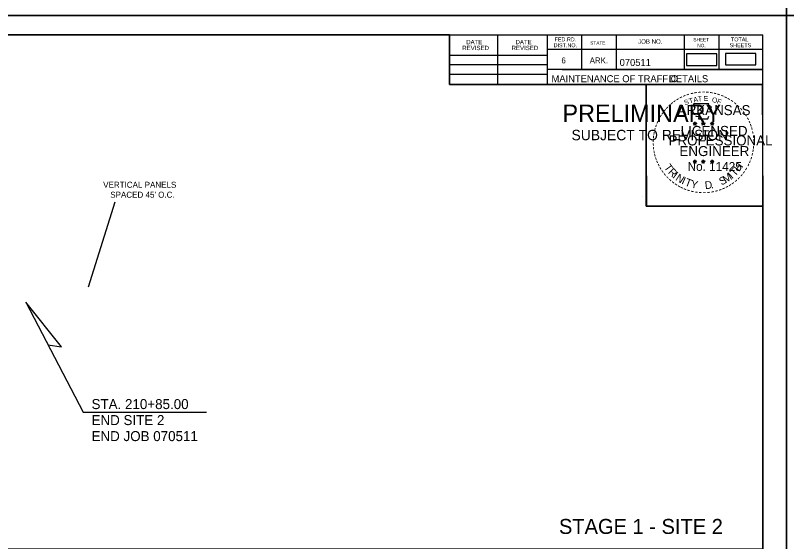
# Model space of a CAD drawing. Extents: x 1398460 to 1408037, y 380768 to 383968.
# Drawn here: x 1401561 to 1402332, y 381308 to 381834 of the extents above; entities that cross this region are included whole.
import ezdxf

# ---------------------------------------------------------------- set-up
doc = ezdxf.new("R2010")
doc.units = 0
for name, color, linetype in [('Default', 7, 'Continuous'), ('MOT STAGE ALL', 7, 'Continuous'), ('R_Border', 7, 'Continuous'), ('R_Border PE', 7, 'Continuous'), ('R_Border Prem', 7, 'Continuous'), ('R_Dimension', 7, 'Continuous'), ('R_MOT', 7, 'Continuous'), ('R_No Plot', 7, 'Continuous')]:
    doc.layers.add(name, color=color, linetype=linetype)

msp = doc.modelspace()

# ---------------------------------------------------------------- linework, layer by layer
at = {"layer": 'Default'}
for p, q in [((1401571.6, 381547.85), (1401628.93, 381437.94)), ((1401628.93, 381437.94), (1401752.42, 381437.94))]:
    msp.add_line(p, q, dxfattribs=at)
msp.add_lwpolyline([(1401593.87, 381505.15), (1401607.48, 381503.17), (1401571.6, 381547.85)], dxfattribs=at)
at = {"layer": 'R_Border'}
for p, q in [((1400727.57, 381814.73), (1402308.47, 381814.73)), ((1401995.27, 381765.33), (1401995.27, 381814.73)), ((1402043.67, 381765.33), (1402043.67, 381814.73)), ((1402092.97, 381814.73), (1402092.97, 381765.33)), ((1402127.17, 381814.73), (1402127.17, 381780.03)), ((1402161.87, 381814.73), (1402161.87, 381780.03)), ((1402229.77, 381814.73), (1402229.77, 381780.03)), ((1402264.47, 381814.73), (1402264.47, 381780.03)), ((1402308.47, 380787.43), (1402308.47, 381814.73)), ((1402308.47, 381800.03), (1402092.97, 381800.03)), ((1402308.47, 381800.13), (1402308.47, 381800.13)), ((1401995.27, 381794.63), (1402092.97, 381794.63)), ((1401995.27, 381785.33), (1402092.97, 381785.33)), ((1401995.27, 381775.63), (1402092.97, 381775.63)), ((1402308.47, 381780.03), (1402092.97, 381780.03)), ((1402107.77, 381780.03), (1402308.47, 381780.03)), ((1402308.47, 381765.33), (1401995.27, 381765.33))]:
    msp.add_line(p, q, dxfattribs=at)
at = {"layer": 'R_Border PE'}
for p, q in [((1402238.89, 381726.61), (1402240.64, 381726.05)), ((1402238.89, 381726.61), (1402240.16, 381726.38)), ((1402238.89, 381726.61), (1402240.08, 381726)), ((1402239.56, 381724.57), (1402240.64, 381726.05)), ((1402239.56, 381724.57), (1402240.19, 381725.79)), ((1402239.56, 381724.57), (1402240.63, 381725.65)), ((1402240.64, 381727.88), (1402240.43, 381726.62)), ((1402241.7, 381724.57), (1402240.63, 381725.64)), ((1402240.64, 381726.05), (1402240.64, 381727.88)), ((1402240.64, 381727.88), (1402240.88, 381726.63)), ((1402242.37, 381726.61), (1402240.64, 381726.05)), ((1402241.7, 381724.57), (1402240.64, 381726.05)), ((1402242.37, 381726.61), (1402240.94, 381726.36)), ((1402241.7, 381724.57), (1402241.02, 381726.02)), ((1402242.37, 381726.61), (1402241.35, 381726.1)), ((1402247.24, 381726.61), (1402248.99, 381726.05)), ((1402247.24, 381726.61), (1402248.51, 381726.38)), ((1402247.24, 381726.61), (1402248.43, 381726)), ((1402247.91, 381724.57), (1402248.99, 381726.05)), ((1402247.91, 381724.57), (1402248.54, 381725.79)), ((1402247.91, 381724.57), (1402248.98, 381725.65)), ((1402248.99, 381727.88), (1402248.78, 381726.62)), ((1402250.05, 381724.57), (1402248.98, 381725.64)), ((1402248.99, 381726.05), (1402248.99, 381727.88)), ((1402248.99, 381727.88), (1402249.23, 381726.63)), ((1402250.72, 381726.61), (1402248.99, 381726.05)), ((1402250.05, 381724.57), (1402248.99, 381726.05)), ((1402250.72, 381726.61), (1402249.29, 381726.36)), ((1402250.05, 381724.57), (1402249.37, 381726.02)), ((1402250.72, 381726.61), (1402249.7, 381726.1)), ((1402256.06, 381726.55), (1402257.81, 381725.99)), ((1402256.06, 381726.55), (1402257.33, 381726.32)), ((1402256.06, 381726.55), (1402257.25, 381725.94)), ((1402256.73, 381724.51), (1402257.81, 381725.99)), ((1402256.73, 381724.51), (1402257.36, 381725.73)), ((1402256.73, 381724.51), (1402257.8, 381725.59)), ((1402257.81, 381727.82), (1402257.6, 381726.56)), ((1402258.87, 381724.51), (1402257.8, 381725.58)), ((1402257.81, 381725.99), (1402257.81, 381727.82)), ((1402257.81, 381727.82), (1402258.05, 381726.57)), ((1402259.54, 381726.55), (1402257.81, 381725.99)), ((1402258.87, 381724.51), (1402257.81, 381725.99)), ((1402259.54, 381726.55), (1402258.11, 381726.3)), ((1402258.87, 381724.51), (1402258.19, 381725.96)), ((1402259.54, 381726.55), (1402258.52, 381726.04)), ((1402238.87, 381688.74), (1402240.62, 381688.19)), ((1402238.87, 381688.74), (1402240.14, 381688.52)), ((1402238.87, 381688.74), (1402240.06, 381688.13)), ((1402239.54, 381686.7), (1402240.62, 381688.19)), ((1402239.54, 381686.7), (1402240.17, 381687.92)), ((1402239.54, 381686.7), (1402240.61, 381687.79)), ((1402240.62, 381690.01), (1402240.41, 381688.75)), ((1402241.68, 381686.7), (1402240.61, 381687.77)), ((1402240.62, 381688.19), (1402240.62, 381690.01)), ((1402240.62, 381690.01), (1402240.86, 381688.76)), ((1402242.35, 381688.74), (1402240.62, 381688.19)), ((1402241.68, 381686.7), (1402240.62, 381688.19)), ((1402242.35, 381688.74), (1402240.92, 381688.5)), ((1402241.68, 381686.7), (1402241, 381688.16)), ((1402242.35, 381688.74), (1402241.33, 381688.23)), ((1402247.22, 381688.74), (1402248.96, 381688.19)), ((1402247.22, 381688.74), (1402248.48, 381688.52)), ((1402247.22, 381688.74), (1402248.4, 381688.13)), ((1402247.88, 381686.7), (1402248.96, 381688.19)), ((1402247.88, 381686.7), (1402248.51, 381687.92)), ((1402247.88, 381686.7), (1402248.95, 381687.79)), ((1402248.96, 381690.01), (1402248.76, 381688.75)), ((1402250.03, 381686.7), (1402248.95, 381687.77)), ((1402248.96, 381688.19), (1402248.96, 381690.01)), ((1402248.96, 381690.01), (1402249.21, 381688.76)), ((1402250.7, 381688.74), (1402248.96, 381688.19)), ((1402250.03, 381686.7), (1402248.96, 381688.19)), ((1402250.7, 381688.74), (1402249.27, 381688.5)), ((1402250.03, 381686.7), (1402249.34, 381688.16)), ((1402250.7, 381688.74), (1402249.68, 381688.23)), ((1402256.05, 381688.69), (1402257.8, 381688.14)), ((1402256.05, 381688.69), (1402257.32, 381688.47)), ((1402256.05, 381688.69), (1402257.24, 381688.08)), ((1402256.72, 381686.65), (1402257.8, 381688.14)), ((1402256.72, 381686.65), (1402257.35, 381687.87)), ((1402256.72, 381686.65), (1402257.79, 381687.74)), ((1402257.8, 381689.96), (1402257.59, 381688.7)), ((1402258.86, 381686.65), (1402257.79, 381687.72)), ((1402257.8, 381688.14), (1402257.8, 381689.96)), ((1402257.8, 381689.96), (1402258.04, 381688.71)), ((1402259.53, 381688.69), (1402257.8, 381688.14)), ((1402258.86, 381686.65), (1402257.8, 381688.14)), ((1402259.53, 381688.69), (1402258.1, 381688.45)), ((1402258.86, 381686.65), (1402258.18, 381688.11)), ((1402259.53, 381688.69), (1402258.51, 381688.18))]:
    msp.add_line(p, q, dxfattribs=at)
for points in [[(1402239.1, 381746), (1402240.44, 381741.86)], [(1402256.65, 381741.39), (1402257.36, 381742.81), (1402253.94, 381742.69), (1402254.68, 381746), (1402239.1, 381746)], [(1402241.56, 381733.88), (1402241.56, 381733.45), (1402244.37, 381733.35), (1402244.1, 381730.99), (1402253.45, 381730.99), (1402254.46, 381733.67)], [(1402240.64, 381727.88), (1402241.7, 381724.57), (1402238.89, 381726.61), (1402242.37, 381726.61), (1402239.56, 381724.57), (1402240.64, 381727.88)], [(1402248.99, 381727.88), (1402250.05, 381724.57), (1402247.24, 381726.61), (1402250.72, 381726.61), (1402247.91, 381724.57), (1402248.99, 381727.88)], [(1402257.81, 381727.82), (1402258.87, 381724.51), (1402256.06, 381726.55), (1402259.54, 381726.55), (1402256.73, 381724.51), (1402257.81, 381727.82)], [(1402240.62, 381690.01), (1402241.68, 381686.7), (1402238.87, 381688.74), (1402242.35, 381688.74), (1402239.54, 381686.7), (1402240.62, 381690.01)], [(1402248.96, 381690.01), (1402250.03, 381686.7), (1402247.22, 381688.74), (1402250.7, 381688.74), (1402247.88, 381686.7), (1402248.96, 381690.01)], [(1402257.8, 381689.96), (1402258.86, 381686.65), (1402256.05, 381688.69), (1402259.53, 381688.69), (1402256.72, 381686.65), (1402257.8, 381689.96)]]:
    msp.add_lwpolyline(points, dxfattribs=at)
for centre, radius in [((1402240.63, 381726.05), 0.861), ((1402240.63, 381726.05), 0.723), ((1402240.63, 381726.05), 0.579), ((1402240.63, 381726.05), 0.495), ((1402240.63, 381726.05), 0.374), ((1402240.63, 381726.05), 0.248), ((1402240.63, 381726.05), 0.148), ((1402248.98, 381726.05), 0.861), ((1402248.98, 381726.05), 0.723), ((1402248.98, 381726.05), 0.579), ((1402248.98, 381726.05), 0.495), ((1402248.98, 381726.05), 0.374), ((1402248.98, 381726.05), 0.248), ((1402248.98, 381726.05), 0.148), ((1402257.8, 381725.99), 0.861), ((1402257.8, 381725.99), 0.723), ((1402257.8, 381725.99), 0.579), ((1402257.8, 381725.99), 0.495), ((1402257.8, 381725.99), 0.374), ((1402257.8, 381725.99), 0.248), ((1402257.8, 381725.99), 0.148), ((1402240.61, 381688.18), 0.861), ((1402240.61, 381688.18), 0.723), ((1402240.61, 381688.18), 0.579), ((1402240.61, 381688.18), 0.495), ((1402240.61, 381688.18), 0.374), ((1402240.61, 381688.18), 0.248), ((1402240.61, 381688.18), 0.148), ((1402248.96, 381688.18), 0.861), ((1402248.96, 381688.18), 0.723), ((1402248.96, 381688.18), 0.579), ((1402248.96, 381688.18), 0.495), ((1402248.96, 381688.18), 0.374), ((1402248.96, 381688.18), 0.248), ((1402248.96, 381688.18), 0.148), ((1402257.79, 381688.13), 0.861), ((1402257.79, 381688.13), 0.723), ((1402257.79, 381688.13), 0.579), ((1402257.79, 381688.13), 0.495), ((1402257.79, 381688.13), 0.374), ((1402257.79, 381688.13), 0.248), ((1402257.79, 381688.13), 0.148)]:
    msp.add_circle(centre, radius, dxfattribs=at)
at = {"layer": 'R_Dimension'}
for points in [[(1402232.31, 381784.13), (1402262.58, 381784.13), (1402262.58, 381795.68), (1402232.31, 381795.68)], [(1402271.1, 381784.76), (1402301.37, 381784.76), (1402301.37, 381796.32), (1402271.1, 381796.32)]]:
    msp.add_lwpolyline(points, close=True, dxfattribs=at)
at = {"layer": 'R_MOT'}
msp.add_line((1401634.48, 381563.14), (1401661.1, 381647.99), dxfattribs=at)
at = {"layer": 'R_No Plot'}
for p, q in [((1400665.56, 381834.2), (1402332.23, 381834.2)), ((1402188.64, 381653.05), (1402188.64, 381653.05))]:
    msp.add_line(p, q, dxfattribs=at)
for points in [[(1400665.53, 382900.89), (1402332.23, 382900.89), (1402332.23, 381834.2), (1400665.53, 381834.2)], [(1402332.23, 382900.89), (1403998.93, 382900.89), (1403998.93, 381834.2), (1402332.23, 381834.2)], [(1400665.53, 381834.2), (1402332.23, 381834.2), (1402332.23, 380767.52), (1400665.53, 380767.52)], [(1402332.23, 381834.2), (1403998.93, 381834.2), (1403998.93, 380767.52), (1402332.23, 380767.52)], [(1400727.57, 381814.73), (1400727.57, 380787.43), (1402308.47, 380787.43), (1402308.47, 381643.67), (1402191.82, 381643.67), (1402191.82, 381765.33), (1401995.27, 381765.33), (1401995.27, 381814.73)], [(1400727.57, 381814.73), (1400727.57, 381301.08), (1402308.47, 381301.08), (1402308.47, 381643.67), (1402191.82, 381643.67), (1402191.82, 381765.33), (1401995.27, 381765.33), (1401995.27, 381814.73)], [(1401897.17, 381814.73), (1401995.27, 381814.73), (1401995.27, 381765.33), (1402075.83, 381765.33), (1402191.82, 381765.33), (1402191.82, 381643.67), (1402308.47, 381643.67), (1402308.47, 380787.43), (1400727.57, 380787.43), (1400727.57, 381814.73)], [(1402191.82, 381765.33), (1402307.86, 381765.33), (1402308.47, 381643.67), (1402192.43, 381643.67)]]:
    msp.add_lwpolyline(points, close=True, dxfattribs=at)

# ---------------------------------------------------------------- texts
at = {"layer": 'MOT STAGE ALL'}
for s, p in [('VERTICAL PANELS', (1401649.08, 381662)), ("SPACED 45' O.C. ", (1401656.16, 381652.04))]:
    msp.add_text(s, height=6.0001, rotation=0, dxfattribs=at).set_placement(p)
at = {"layer": 'R_Border'}
for s, height, p in [('DATE', 4.396, (1402011.96, 381805.41)), ('DATE', 4.396, (1402061.26, 381805.41)), ('DIST.NO.', 3.91, (1402099.37, 381802.43)), ('FED.RD.', 3.91, (1402100.37, 381808.33)), ('STATE', 3.42, (1402135.97, 381804.93)), ('JOB NO.', 4.396, (1402183.87, 381805.93)), ('SHEET', 3.42, (1402239.07, 381808.33)), ('NO.', 3.42, (1402242.97, 381802.43)), ('SHEETS', 3.91, (1402275.27, 381802.43)), ('TOTAL', 3.91, (1402276.67, 381808.33)), ('REVISED', 4.396, (1402008.06, 381799.51)), ('REVISED', 4.396, (1402057.36, 381799.51)), ('6', 5.86, (1402107.17, 381786.33)), ('ARK.', 5.861, (1402135.47, 381786.33)), ('070511', 7, (1402165.35, 381783.73)), ('MAINTENANCE OF TRAFFIC', 7, (1402097.28, 381767.48)), (' DETAILS', 7, (1402212.28, 381767.48)), ('STAGE 1 - SITE 2 ', 15, (1402104.69, 381316.1))]:
    msp.add_text(s, height=height, dxfattribs=at).set_placement(p)
at = {"layer": 'R_Border PE'}
for s, height, rotation, p in [('-', 8, 28.79182, (1402226.5, 381748.7)), ('-', 8, 24.30721, (1402229.67, 381750.29)), ('-', 8, 19.17608, (1402232.84, 381751.63)), ('T', 5, 16.4036, (1402235.44, 381746.04)), ('-', 8, 13.63015, (1402236.59, 381752.84)), ('A', 5, 11.21318, (1402239.57, 381747.3)), ('-', 8, 10.21935, (1402239.98, 381753.65)), ('T', 5, 6.02276, (1402243.82, 381748.13)), ('-', 8, 5.89682, (1402243.62, 381754.2)), ('-', 8, 0.18623, (1402247.48, 381754.56)), ('E', 5, 0.83234, (1402249.34, 381748.68)), ('-', 8, 357.74304, (1402251.1, 381754.49)), ('-', 8, 352.16172, (1402254.82, 381754.21)), ('O', 5, 350.4515, (1402257.36, 381747.63)), ('-', 8, 347.20489, (1402258.41, 381753.64)), ('-', 8, 342.3362, (1402261.59, 381752.87)), ('-', 8, 337.85509, (1402265.26, 381751.75)), ('-', 8, 334.12109, (1402268.42, 381750.4)), ('-', 8, 329.64089, (1402271.31, 381748.98)), ('-', 8, 42.96224, (1402216.08, 381740.9)), ('-', 8, 38.95066, (1402218.25, 381742.99)), ('-', 8, 36.23174, (1402220.63, 381744.88)), ('-', 8, 34.06357, (1402223.52, 381746.85)), ('S', 5, 21.59401, (1402230.87, 381744.39)), ('F', 5, 340.07066, (1402262.13, 381746.49)), ('-', 8, 325.86266, (1402274.53, 381747.18)), ('-', 8, 320.52971, (1402277.58, 381745.05)), ('-', 8, 315.57859, (1402280.57, 381742.61)), ('-', 8, 54.23247, (1402209.76, 381733.25)), ('-', 8, 50.61417, (1402211.83, 381736.08)), ('-', 8, 48.42305, (1402213.84, 381738.51)), ('-', 8, 309.87973, (1402283.42, 381739.86)), ('-', 8, 306.65218, (1402286.04, 381736.85)), ('-', 8, 67.77427, (1402205.28, 381724.49)), ('-', 8, 62.87135, (1402206.57, 381727.54)), ('-', 8, 58.07063, (1402208.14, 381730.61)), ('-', 7, 303.67529, (1402288.47, 381734.01)), ('-', 8, 299.66835, (1402290.07, 381730.97)), ('-', 8, 294.66279, (1402291.69, 381727.91)), ('-', 8, 75.46096, (1402203.2, 381717.77)), ('-', 8, 72.39447, (1402204.18, 381721.34)), ('-', 8, 290.57283, (1402292.97, 381725.03)), ('-', 8, 285.12326, (1402294.14, 381722.13)), ('-', 8, 85.18634, (1402202.16, 381710.75)), ('-', 8, 81.20126, (1402202.54, 381714.2)), ('-', 8, 280.54934, (1402295.14, 381718.42)), ('-', 8, 276.59616, (1402295.95, 381714.58)), ('-', 8, 94.19588, (1402202.21, 381703.62)), ('-', 8, 89.06224, (1402202.03, 381707.24)), ('-', 8, 274.33011, (1402296.25, 381710.97)), ('-', 8, 269.94067, (1402296.42, 381707.81)), ('-', 8, 98.94793, (1402202.57, 381700.28)), ('-', 8, 101.71495, (1402203.24, 381696.62)), ('-', 8, 260.99529, (1402295.97, 381701.21)), ('-', 8, 263.5172, (1402296.33, 381704.48)), ('-', 8, 105.45785, (1402204.05, 381693.64)), ('-', 8, 109.08742, (1402205.13, 381690.49)), ('-', 8, 252.86809, (1402294.52, 381694.22)), ('-', 8, 255.7626, (1402295.42, 381697.82)), ('-', 8, 114.06432, (1402206.4, 381687.51)), ('-', 8, 115.72885, (1402207.92, 381684.42)), ('-', 8, 120.44712, (1402209.71, 381681.49)), ('T', 7.7, 306.04056, (1402209.41, 381682.38)), ('T', 7.7, 46.64442, (1402280.57, 381672.84)), ('H', 7.7, 54.60883, (1402285.01, 381677.55)), ('-', 8, 244.61971, (1402292.09, 381687.71)), ('-', 8, 247.88866, (1402293.4, 381690.85)), ('-', 8, 125.89344, (1402211.72, 381678.68)), ('-', 8, 130.71812, (1402214.03, 381675.92)), ('R', 7.7, 314.00497, (1402213.23, 381677.14)), ('I', 7.7, 321.96938, (1402217.73, 381672.48)), ('N', 7.7, 326.50021, (1402220.56, 381670.12)), ('M', 7.7, 32.65632, (1402271.34, 381666.22)), ('I', 7.7, 42.11359, (1402277.76, 381670.45)), ('-', 8, 231.25377, (1402285.96, 381677.85)), ('-', 8, 233.84524, (1402288.11, 381680.68)), ('-', 8, 239.07125, (1402290.12, 381683.95)), ('-', 8, 134.22381, (1402216.62, 381673.2)), ('-', 8, 138.93382, (1402219.24, 381670.88)), ('-', 8, 144.64634, (1402222.02, 381668.85)), ('I', 7.7, 335.36034, (1402226.61, 381666.19)), ('T', 7.7, 339.89117, (1402229.91, 381664.55)), ('Y', 7.7, 347.85558, (1402236, 381662.33)), ('D', 7.7, 6.39691, (1402250.92, 381660.53)), ('S', 7.7, 26.9312, (1402267.14, 381664.19)), ('-', 8, 215.73633, (1402278.21, 381670.13)), ('-', 8, 221.08509, (1402280.96, 381672.49)), ('-', 8, 225.76533, (1402283.57, 381675.03)), ('-', 8, 148.08978, (1402224.83, 381666.99)), ('-', 8, 151.57039, (1402227.72, 381665.37)), ('-', 8, 154.60019, (1402230.33, 381664.13)), ('-', 8, 158.56121, (1402233.45, 381662.86)), ('-', 8, 162.79826, (1402236.89, 381661.8)), ('.', 7.7, 13.76417, (1402256.88, 381661.17)), ('-', 8, 195.47429, (1402263.15, 381662.29)), ('-', 8, 200.71842, (1402266.54, 381663.5)), ('-', 8, 204.25161, (1402269.63, 381664.87)), ('-', 8, 207.35684, (1402272.75, 381666.46)), ('-', 8, 212.24909, (1402275.54, 381668.19)), ('-', 8, 167.55551, (1402240.46, 381660.98)), ('-', 8, 173.11546, (1402244.32, 381660.43)), ('-', 8, 176.51827, (1402248.06, 381660.16)), ('-', 8, 181.59176, (1402251.78, 381660.26)), ('-', 8, 185.81666, (1402255.83, 381660.64)), ('-', 8, 191.28576, (1402259.51, 381661.3))]:
    msp.add_text(s, height=height, rotation=rotation, dxfattribs=at).set_placement(p)
for s, height, p in [('ARKANSAS', 10, (1402223.36, 381734.56)), ('LICENSED', 10, (1402226.35, 381713.81)), ('DWB', 0.05, (1402240.57, 381726.02)), ('DWB', 0.05, (1402248.92, 381726.02)), ('DWB', 0.05, (1402257.74, 381725.97)), ('PROFESSIONAL', 10, (1402214.23, 381704.29)), ('ENGINEER', 10, (1402225.17, 381693.67)), ('No. 11425', 8.785, (1402233.3, 381678.91)), ('DWB', 0.05, (1402240.55, 381688.16)), ('DWB', 0.05, (1402248.9, 381688.16)), ('DWB', 0.05, (1402257.73, 381688.11))]:
    msp.add_text(s, height=height, dxfattribs=at).set_placement(p)
at = {"layer": 'R_Border Prem'}
for s, height, p in [('PRELIMINARY', 17.5, (1402108.22, 381727.65)), ('DWB', 0.05, (1402111.96, 381736.89)), ('SUBJECT TO REVISION', 10.3756, (1402117.27, 381709.5))]:
    msp.add_text(s, height=height, dxfattribs=at).set_placement(p)
at = {"layer": 'R_Dimension'}
for s, p in [('STA. 210+85.00', (1401637.46, 381440.86)), ('END SITE 2', (1401637.46, 381424.86)), ('END JOB 070511', (1401637.46, 381408.86))]:
    msp.add_text(s, height=10, dxfattribs=at).set_placement(p)

doc.saveas('drawing.dxf')
